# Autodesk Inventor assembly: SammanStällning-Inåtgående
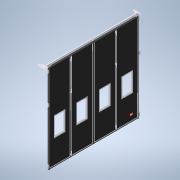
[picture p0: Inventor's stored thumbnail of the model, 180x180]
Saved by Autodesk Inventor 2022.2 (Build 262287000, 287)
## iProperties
Created: 2022-02
Part Number: SammanStällning-Inåtgående
Document SubType Name: Assembly
Designer: cl
Author: cl
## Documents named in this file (19)
- G:\AutoCad\Carl Lund\3D-modeller systemlösningar\3D-modell-systemlösning-2022\SammanStällning-Inåtgående.iam
- G:\AutoCad\Carl Lund\3D-modeller systemlösningar\3D-modell-systemlösning-2022\Parts\BladKomplett2022.iam
- G:\AutoCad\Carl Lund\3D-modeller systemlösningar\3D-modell-systemlösning-2022\Parts\MellanGångjärnH.ipt
- G:\AutoCad\Carl Lund\3D-modeller systemlösningar\3D-modell-systemlösning-2022\Parts\MellanGångjärnV.ipt
- G:\AutoCad\Carl Lund\3D-modeller systemlösningar\3D-modell-systemlösning-2022\Parts\Karmstyrning.ipt
- G:\AutoCad\Carl Lund\3D-modeller systemlösningar\3D-modell-systemlösning-2022\Parts\KarmgångjärnH.ipt
- G:\AutoCad\Carl Lund\3D-modeller systemlösningar\3D-modell-systemlösning-2022\Parts\KarmgångjärnV.ipt
- G:\AutoCad\Carl Lund\3D-modeller systemlösningar\3D-modell-systemlösning-2022\Parts\SidotätningUppe.ipt
- G:\AutoCad\Carl Lund\3D-modeller systemlösningar\3D-modell-systemlösning-2022\Parts\SidoTätning.ipt
- G:\AutoCad\Carl Lund\3D-modeller systemlösningar\3D-modell-systemlösning-2022\Parts\SläpList.ipt
- G:\AutoCad\Carl Lund\3D-modeller systemlösningar\3D-modell-systemlösning-2022\Parts\GummilistMellan.ipt
- G:\AutoCad\Carl Lund\3D-modeller systemlösningar\3D-modell-systemlösning-2022\Styrande.iam
- G:\AutoCad\Carl Lund\3D-modeller systemlösningar\3D-modell-systemlösning-2022\Parts\GarageregelHöger.ipt
- G:\AutoCad\Carl Lund\3D-modeller systemlösningar\3D-modell-systemlösning-2022\Parts\GarageregelVänster.ipt
- G:\AutoCad\Carl Lund\3D-modeller systemlösningar\3D-modell-systemlösning-2022\Parts\UppställningsbeslagHöger.ipt
- G:\AutoCad\Carl Lund\3D-modeller systemlösningar\3D-modell-systemlösning-2022\Parts\UppställningsbeslagVänster.ipt
- G:\AutoCad\Carl Lund\3D-modeller systemlösningar\3D-modell-systemlösning-2022\Parts\styrrulle.ipt
- G:\AutoCad\Carl Lund\3D-modeller systemlösningar\3D-modell-systemlösning-2022\Parts\Styrskena.ipt
- G:\AutoCad\Carl Lund\3D-modeller systemlösningar\3D-modell-systemlösning-2022\Parts\Logga.ipt
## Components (44 placed, 17 different names)
1. BladKomplett2022:1 [sub-assembly] — Mate:1, Mate:2, Flush:1, Flush:2, Flush:3, Flush:8, Flush:28, Flush:29, Mate:28, Flush:30, Mate:42, Flush:73, Mate:39, Mate:43, Mate:47, Mate:48, Flush:99, Flush:100, Flush:101, Flush:102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
2. BladKomplett2022:2 [sub-assembly] — Flush:2, Flush:3, Flush:8, Flush:106, Mate:52, Flush:107, Flush:118, Flush:121, Mate:65, Flush:148, Flush:149, Mate:82, Flush:170, Flush:171
3. BladKomplett2022:3 [sub-assembly] — Flush:30, Flush:101, Flush:102, Mate:53, Flush:114, Flush:115
4. BladKomplett2022:4 [sub-assembly] — Flush:32, Flush:100, Flush:103, Mate:54, Flush:122, Flush:123, Flush:128, Mate:64, Flush:146, Flush:147, Mate:177
5. BladKomplett2022:5 [sub-assembly] — Flush:31, Flush:99, Flush:104, Flush:129, Mate:55, Flush:130, Mate:63, Flush:144, Flush:145, Mate:81, Flush:168, Flush:169
6. Logga:1 — Mate:177, Mate:178, Mate:179
7. BladKomplett2022:6 [sub-assembly] — Mate:28, Flush:28, Flush:29, Flush:31, Flush:32, Mate:38, Flush:74, Mate:49, Mate:50, Flush:131, Flush:134, Flush:137, Mate:56, Flush:138, Flush:139, Mate:58, Mate:59, Mate:62, Flush:142, Flush:143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
8. GarageregelHöger:1 — Flush:156, Flush:157, Flush:158
9. GarageregelHöger:2 — Mate:77, Flush:154, Flush:155, Flush:156, Flush:157, Flush:158
10. GarageregelVänster:1 — Flush:161, Flush:162, Flush:163
11. GarageregelVänster:2 — Mate:78, Flush:159, Flush:160, Flush:161, Flush:162, Flush:163
12. Karmstyrning:2 — Mate:38, Mate:56, Flush:138, Flush:141
13. Karmstyrning:3 — Mate:39, Mate:43, Flush:140
14. Karmstyrning:4 — Mate:42, Mate:60, Mate:61, Flush:141
15. KarmgångjärnH:1 — Flush:74, Mate:49, Mate:50, Flush:166, Flush:167, Mate:80
16. KarmgångjärnV:1 — Flush:73, Mate:47, Mate:48, Flush:164, Flush:165, Mate:79
17. Karmstyrning:1 — Flush:139, Mate:58, Mate:59, Flush:140
18. MellanGångjärnV:3 — Flush:110, Flush:111, Flush:113
19. MellanGångjärnV:2 — Flush:108, Flush:109, Flush:110, Flush:111, Flush:112
20. MellanGångjärnV:1 — Flush:106, Mate:52, Flush:107, Flush:108, Flush:109
21. MellanGångjärnH:2 — Flush:116, Flush:117, Flush:118, Flush:119, Flush:120
22. MellanGångjärnH:3 — Flush:119, Flush:120, Flush:121
23. MellanGångjärnH:1 — Mate:53, Flush:114, Flush:115, Flush:116, Flush:117
24. MellanGångjärnV:6 — Flush:124, Flush:125, Flush:126, Flush:127, Flush:128
25. MellanGångjärnV:5 — Flush:126, Flush:127, Flush:129
26. MellanGångjärnV:4 — Mate:54, Flush:122, Flush:123, Flush:124, Flush:125
27. MellanGångjärnH:5 — Flush:132, Flush:133, Flush:134
28. MellanGångjärnH:6 — Flush:135, Flush:136, Flush:137
29. MellanGångjärnH:4 — Mate:55, Flush:130, Flush:131, Flush:132, Flush:133, Flush:135, Flush:136
30. GummilistMellan:2 — Mate:63, Flush:144, Flush:145
31. GummilistMellan:3 — Mate:64, Flush:146, Flush:147
32. GummilistMellan:4 — Mate:65, Flush:148, Flush:149
33. GummilistMellan:5 — Mate:66, Flush:150, Flush:151
34. SidotätningUppe:1 — Mate:67, Mate:68, Flush:152, Mate:71, Mate:74
35. SidoTätning:1 — Mate:69, Mate:70, Mate:71, Mate:76
36. SidoTätning:2 — Mate:72, Mate:73, Mate:74
37. SläpList:1 — Mate:75, Flush:153, Mate:76
38. GummilistMellan:1 — Mate:62, Flush:142, Flush:143
39. UppställningsbeslagVänster:1 — Flush:166, Flush:167, Mate:80
40. styrrulle:1 — Mate:81, Flush:168, Flush:169
41. styrrulle:2 — Mate:82, Flush:170, Flush:171, Tangent:1
42. Styrskena:1 — Mate:83, Flush:172, Tangent:1, Flush:174, Mate:176, Flush:175
43. Styrskena:2 — Flush:174, Mate:176, Flush:175
44. UppställningsbeslagHöger:1 — Flush:164, Flush:165, Mate:79, Mate:83, Flush:172
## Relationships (133: Flush 86, Mate 46, Tangent 1)
- Mate:1: BladKomplett2022:1
- Mate:2: BladKomplett2022:1
- Flush:1: BladKomplett2022:1
- Flush:2: BladKomplett2022:1 ↔ BladKomplett2022:2
- Flush:3: BladKomplett2022:1 ↔ BladKomplett2022:2
- Flush:8: BladKomplett2022:1 ↔ BladKomplett2022:2
- Mate:28: BladKomplett2022:1 ↔ BladKomplett2022:6
- Flush:28: BladKomplett2022:1 ↔ BladKomplett2022:6
- Flush:29: BladKomplett2022:1 ↔ BladKomplett2022:6
- Flush:30: BladKomplett2022:1 ↔ BladKomplett2022:3
- Flush:31: BladKomplett2022:5 ↔ BladKomplett2022:6
- Flush:32: BladKomplett2022:4 ↔ BladKomplett2022:6
- Mate:38: BladKomplett2022:6 ↔ Karmstyrning:2
- Mate:39: BladKomplett2022:1 ↔ Karmstyrning:3
- Mate:42: BladKomplett2022:1 ↔ Karmstyrning:4
- Mate:43: BladKomplett2022:1 ↔ Karmstyrning:3
- Flush:73: BladKomplett2022:1 ↔ KarmgångjärnV:1
- Mate:47: BladKomplett2022:1 ↔ KarmgångjärnV:1
- Mate:48: BladKomplett2022:1 ↔ KarmgångjärnV:1
- Flush:74: BladKomplett2022:6 ↔ KarmgångjärnH:1
- Mate:49: BladKomplett2022:6 ↔ KarmgångjärnH:1
- Mate:50: BladKomplett2022:6 ↔ KarmgångjärnH:1
- Flush:99: BladKomplett2022:1 ↔ BladKomplett2022:5
- Flush:100: BladKomplett2022:1 ↔ BladKomplett2022:4
- Flush:101: BladKomplett2022:1 ↔ BladKomplett2022:3
- Flush:102: BladKomplett2022:1 ↔ BladKomplett2022:3
- Flush:103: BladKomplett2022:1 ↔ BladKomplett2022:4
- Flush:104: BladKomplett2022:1 ↔ BladKomplett2022:5
- Flush:106: BladKomplett2022:2 ↔ MellanGångjärnV:1
- Mate:52: BladKomplett2022:2 ↔ MellanGångjärnV:1
- Flush:107: BladKomplett2022:2 ↔ MellanGångjärnV:1
- Flush:108: MellanGångjärnV:2 ↔ MellanGångjärnV:1
- Flush:109: MellanGångjärnV:2 ↔ MellanGångjärnV:1
- Flush:110: MellanGångjärnV:3 ↔ MellanGångjärnV:2
- Flush:111: MellanGångjärnV:3 ↔ MellanGångjärnV:2
- Flush:112: BladKomplett2022:1 ↔ MellanGångjärnV:2
- Flush:113: BladKomplett2022:1 ↔ MellanGångjärnV:3
- Mate:53: BladKomplett2022:3 ↔ MellanGångjärnH:1
- Flush:114: BladKomplett2022:3 ↔ MellanGångjärnH:1
- Flush:115: BladKomplett2022:3 ↔ MellanGångjärnH:1
- Flush:116: MellanGångjärnH:2 ↔ MellanGångjärnH:1
- Flush:117: MellanGångjärnH:2 ↔ MellanGångjärnH:1
- Flush:118: BladKomplett2022:2 ↔ MellanGångjärnH:2
- Flush:119: MellanGångjärnH:2 ↔ MellanGångjärnH:3
- Flush:120: MellanGångjärnH:2 ↔ MellanGångjärnH:3
- Flush:121: BladKomplett2022:2 ↔ MellanGångjärnH:3
- Mate:54: BladKomplett2022:4 ↔ MellanGångjärnV:4
- Flush:122: BladKomplett2022:4 ↔ MellanGångjärnV:4
- Flush:123: BladKomplett2022:4 ↔ MellanGångjärnV:4
- Flush:124: MellanGångjärnV:6 ↔ MellanGångjärnV:4
- Flush:125: MellanGångjärnV:6 ↔ MellanGångjärnV:4
- Flush:126: MellanGångjärnV:6 ↔ MellanGångjärnV:5
- Flush:127: MellanGångjärnV:6 ↔ MellanGångjärnV:5
- Flush:128: BladKomplett2022:4 ↔ MellanGångjärnV:6
- Flush:129: BladKomplett2022:5 ↔ MellanGångjärnV:5
- Mate:55: BladKomplett2022:5 ↔ MellanGångjärnH:4
- Flush:130: BladKomplett2022:5 ↔ MellanGångjärnH:4
- Flush:131: BladKomplett2022:6 ↔ MellanGångjärnH:4
- Flush:132: MellanGångjärnH:5 ↔ MellanGångjärnH:4
- Flush:133: MellanGångjärnH:5 ↔ MellanGångjärnH:4
- Flush:134: BladKomplett2022:6 ↔ MellanGångjärnH:5
- Flush:135: MellanGångjärnH:6 ↔ MellanGångjärnH:4
- Flush:136: MellanGångjärnH:6 ↔ MellanGångjärnH:4
- Flush:137: BladKomplett2022:6 ↔ MellanGångjärnH:6
- Mate:56: BladKomplett2022:6 ↔ Karmstyrning:2
- Flush:138: BladKomplett2022:6 ↔ Karmstyrning:2
- Flush:139: BladKomplett2022:6 ↔ Karmstyrning:1
- Mate:58: BladKomplett2022:6 ↔ Karmstyrning:1
- Mate:59: BladKomplett2022:6 ↔ Karmstyrning:1
- Flush:140: Karmstyrning:3 ↔ Karmstyrning:1
- Mate:60: BladKomplett2022:1 ↔ Karmstyrning:4
- Mate:61: BladKomplett2022:1 ↔ Karmstyrning:4
- Flush:141: Karmstyrning:2 ↔ Karmstyrning:4
- Mate:62: BladKomplett2022:6 ↔ GummilistMellan:1
- Flush:142: BladKomplett2022:6 ↔ GummilistMellan:1
- Flush:143: BladKomplett2022:6 ↔ GummilistMellan:1
- Mate:63: BladKomplett2022:5 ↔ GummilistMellan:2
- Flush:144: BladKomplett2022:5 ↔ GummilistMellan:2
- Flush:145: BladKomplett2022:5 ↔ GummilistMellan:2
- Mate:64: BladKomplett2022:4 ↔ GummilistMellan:3
- Flush:146: BladKomplett2022:4 ↔ GummilistMellan:3
- Flush:147: BladKomplett2022:4 ↔ GummilistMellan:3
- Mate:65: BladKomplett2022:2 ↔ GummilistMellan:4
- Flush:148: BladKomplett2022:2 ↔ GummilistMellan:4
- Flush:149: BladKomplett2022:2 ↔ GummilistMellan:4
- Mate:66: BladKomplett2022:1 ↔ GummilistMellan:5
- Flush:150: BladKomplett2022:1 ↔ GummilistMellan:5
- Flush:151: BladKomplett2022:1 ↔ GummilistMellan:5
- Mate:67: BladKomplett2022:1 ↔ SidotätningUppe:1
- Mate:68: BladKomplett2022:1 ↔ SidotätningUppe:1
- Flush:152: BladKomplett2022:6 ↔ SidotätningUppe:1
- Mate:69: BladKomplett2022:6 ↔ SidoTätning:1
- Mate:70: BladKomplett2022:6 ↔ SidoTätning:1
- Mate:71: SidotätningUppe:1 ↔ SidoTätning:1
- Mate:72: BladKomplett2022:1 ↔ SidoTätning:2
- Mate:73: BladKomplett2022:1 ↔ SidoTätning:2
- Mate:74: SidotätningUppe:1 ↔ SidoTätning:2
- Mate:75: BladKomplett2022:1 ↔ SläpList:1
- Flush:153: BladKomplett2022:1 ↔ SläpList:1
- Mate:76: SidoTätning:1 ↔ SläpList:1
- Mate:77: BladKomplett2022:1 ↔ GarageregelHöger:2
- Flush:154: BladKomplett2022:1 ↔ GarageregelHöger:2
- Flush:155: BladKomplett2022:1 ↔ GarageregelHöger:2
- Flush:156: GarageregelHöger:1 ↔ GarageregelHöger:2
- Flush:157: GarageregelHöger:1 ↔ GarageregelHöger:2
- Flush:158: GarageregelHöger:1 ↔ GarageregelHöger:2
- Mate:78: BladKomplett2022:6 ↔ GarageregelVänster:2
- Flush:159: BladKomplett2022:6 ↔ GarageregelVänster:2
- Flush:160: BladKomplett2022:6 ↔ GarageregelVänster:2
- Flush:161: GarageregelVänster:1 ↔ GarageregelVänster:2
- Flush:162: GarageregelVänster:1 ↔ GarageregelVänster:2
- Flush:163: GarageregelVänster:1 ↔ GarageregelVänster:2
- Flush:164: KarmgångjärnV:1 ↔ UppställningsbeslagHöger:1
- Flush:165: KarmgångjärnV:1 ↔ UppställningsbeslagHöger:1
- Mate:79: KarmgångjärnV:1 ↔ UppställningsbeslagHöger:1
- Flush:166: KarmgångjärnH:1 ↔ UppställningsbeslagVänster:1
- Flush:167: KarmgångjärnH:1 ↔ UppställningsbeslagVänster:1
- Mate:80: KarmgångjärnH:1 ↔ UppställningsbeslagVänster:1
- Mate:81: BladKomplett2022:5 ↔ styrrulle:1
- Flush:168: BladKomplett2022:5 ↔ styrrulle:1
- Flush:169: BladKomplett2022:5 ↔ styrrulle:1
- Mate:82: BladKomplett2022:2 ↔ styrrulle:2
- Flush:170: BladKomplett2022:2 ↔ styrrulle:2
- Flush:171: BladKomplett2022:2 ↔ styrrulle:2
- Mate:83: Styrskena:1 ↔ UppställningsbeslagHöger:1
- Flush:172: Styrskena:1 ↔ UppställningsbeslagHöger:1
- Tangent:1: styrrulle:2 ↔ Styrskena:1
- Flush:174: Styrskena:1 ↔ Styrskena:2
- Mate:176: Styrskena:1 ↔ Styrskena:2
- Flush:175: Styrskena:1 ↔ Styrskena:2
- Mate:177: BladKomplett2022:4 ↔ Logga:1
- Mate:178: Logga:1 ↔ BladKomplett2022:6
- Mate:179: Logga:1 ↔ BladKomplett2022:6
## Named parameters: Blad2 = 1012.5 mm, Blad3 = 0, Blad4 = 0, Blad5 = 1012.5 mm, MGJ12Djup = 0, MGJ12Bredd = 0, MGJ56Djup = 0, MGJ56Bredd = 0, MGJ23Djup = 48 mm, MGJ45Djup = 48 mm, GarageRegel5 = 0, GarageRegel6 = 0, BladBredd = 987.5 mm, Fönsterhöjd = 862 mm, Blad2_1 = 1012.5 mm, Blad3_1 = 0, Blad4_1 = 0, Blad5_1 = 1012.5 mm, Blad6 = 2025 mm, MGJ12Djup_1 = 0, MGJ12Bredd_1 = 0, MGJ2Djup = 0, MGJ2Bredd = 5012.5 mm, MGJ56Djup_1 = 0, MGJ56Bredd_1 = 0, MGJ23Djup_1 = 48 mm, MGJ45Djup_1 = 48 mm, GarageRegel5_1 = 0, GarageRegel6_1 = 0, Styrrulle2Djup = 0
